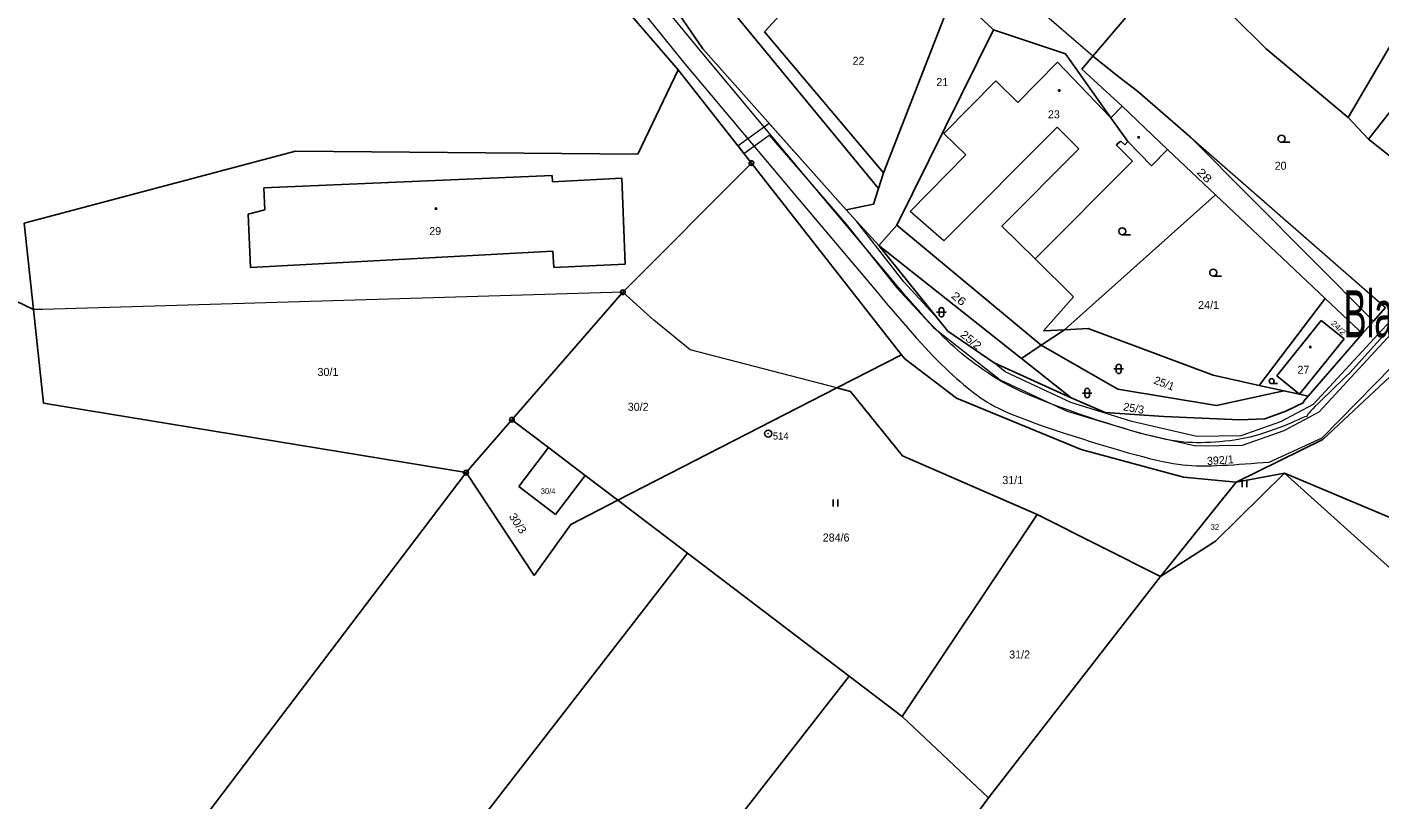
# Model space of a CAD drawing. Extents: x -504006 to -501322, y -1128098 to -1124665.
# Drawn here: x -503112.2 to -502824.9, y -1126824.4 to -1126660.2 of the extents above; entities that cross this region are included whole.
import ezdxf
from ezdxf.enums import TextEntityAlignment as Align

# ---------------------------------------------------------------- set-up
doc = ezdxf.new("R2010")
doc.units = 0
doc.header["$LTSCALE"] = 0.68
for name, color, linetype, lineweight in [('1', 7, 'Continuous', 25), ('13', 7, 'Continuous', 13), ('3', 7, 'Continuous', 25), ('4', 7, 'Continuous', 13), ('5', 7, 'Continuous', 25), ('7', 7, 'Continuous', 13), ('8', 7, 'Continuous', 25)]:
    doc.layers.add(name, color=color, linetype=linetype, lineweight=lineweight)
doc.layers.add('2', color=7, linetype='Continuous')

msp = doc.modelspace()

# ---------------------------------------------------------------- linework, layer by layer
at = {"layer": '1'}
for p, q in [((-503013.32, -1126594.85), (-502931.36, -1126694.5)), ((-502999.07, -1126640.12), (-502973.88, -1126669.24)), ((-502937.19, -1126641.28), (-502955.59, -1126661.2)), ((-502968.7, -1126664.8), (-502982.84, -1126644.09)), ((-502870.5, -1126648.32), (-502885.81, -1126666.36)), ((-502906.97, -1126660.74), (-502914.51, -1126653.68)), ((-502831.61, -1126679.37), (-502817.44, -1126655.15)), ((-502930.28, -1126691.17), (-502916.98, -1126657.04)), ((-502848.99, -1126664.8), (-502856.19, -1126657.72)), ((-502930.28, -1126691.17), (-502955.59, -1126661.2)), ((-502906.97, -1126660.74), (-502927.48, -1126702.25)), ((-502891.65, -1126665.9), (-502906.97, -1126660.74)), ((-502938.24, -1126699.01), (-502968.7, -1126664.8)), ((-502831.61, -1126679.37), (-502848.99, -1126664.8)), ((-502881.99, -1126679.47), (-502891.65, -1126665.9)), ((-502885.81, -1126666.36), (-502888.14, -1126669.11)), ((-502880.27, -1126670.83), (-502885.81, -1126666.36)), ((-502812.52, -1126665.24), (-502827.32, -1126684)), ((-502982.48, -1126687.18), (-502973.88, -1126669.24)), ((-502958.35, -1126689.07), (-502973.88, -1126669.24)), ((-502888.14, -1126669.11), (-502879.6, -1126676.99)), ((-502876.33, -1126673.81), (-502880.27, -1126670.83)), ((-502865.13, -1126683.59), (-502876.33, -1126673.81)), ((-502879.6, -1126676.99), (-502870.01, -1126686.18)), ((-502827.32, -1126684), (-502831.61, -1126679.37)), ((-502878.37, -1126684.47), (-502881.99, -1126679.47)), ((-502879.86, -1126684.43), (-502880.87, -1126685.19)), ((-502880.87, -1126685.19), (-502877.41, -1126688.64)), ((-502879.07, -1126685.19), (-502879.86, -1126684.43)), ((-502878.37, -1126684.47), (-502879.07, -1126685.19)), ((-502873.4, -1126689.68), (-502878.37, -1126684.47)), ((-502826.25, -1126722.68), (-502865.13, -1126683.59)), ((-502813.5, -1126695.01), (-502827.32, -1126684)), ((-503112.79, -1126701.87), (-503055.2, -1126686.52)), ((-503055.2, -1126686.52), (-502982.48, -1126687.18)), ((-502870.01, -1126686.18), (-502873.4, -1126689.68)), ((-502870.01, -1126686.18), (-502859.76, -1126695.85)), ((-502958.35, -1126689.07), (-502985.65, -1126716.51)), ((-502926.46, -1126729.81), (-502958.35, -1126689.07)), ((-502877.41, -1126688.64), (-502898.11, -1126709.4)), ((-503061.88, -1126694.31), (-503000.67, -1126691.74)), ((-503000.67, -1126691.74), (-503000.61, -1126693.03)), ((-503000.61, -1126693.03), (-502985.87, -1126692.31)), ((-502985.87, -1126692.31), (-502985.14, -1126710.59)), ((-502931.36, -1126694.5), (-502930.28, -1126691.17)), ((-503061.69, -1126699), (-503061.88, -1126694.31)), ((-502932.43, -1126697.8), (-502931.36, -1126694.5)), ((-502859.76, -1126695.85), (-502836.46, -1126717.85)), ((-503065.21, -1126699.95), (-503061.69, -1126699)), ((-502938.24, -1126699.01), (-502932.43, -1126697.8)), ((-502931.32, -1126706.59), (-502938.24, -1126699.01)), ((-503110.83, -1126720.22), (-503112.79, -1126701.87)), ((-503064.71, -1126711.28), (-503065.21, -1126699.95)), ((-502927.48, -1126702.25), (-502931.32, -1126706.59)), ((-502896.83, -1126727.8), (-502927.48, -1126702.25)), ((-503000.5, -1126707.79), (-503064.71, -1126711.28)), ((-503000.35, -1126711.25), (-503000.5, -1126707.79)), ((-502916.65, -1126724.77), (-502931.32, -1126706.59)), ((-502931.32, -1126706.59), (-502901, -1126730.57)), ((-503130.35, -1126710.8), (-503110.83, -1126720.22)), ((-502985.14, -1126710.59), (-503000.35, -1126711.25)), ((-502898.11, -1126709.4), (-502889.92, -1126717.49)), ((-502889.92, -1126717.49), (-502896.32, -1126724.74)), ((-502836.46, -1126717.85), (-502850.54, -1126736.32)), ((-502836.46, -1126717.85), (-502830.3, -1126723.67)), ((-503108.71, -1126740.11), (-503110.83, -1126720.22)), ((-502837.31, -1126722.5), (-502846.79, -1126734.26)), ((-502832.45, -1126726.42), (-502837.31, -1126722.5)), ((-502826.25, -1126722.68), (-502823.71, -1126719.75)), ((-502906.76, -1126731.49), (-502916.65, -1126724.77)), ((-502891.83, -1126724.49), (-502896.83, -1126727.8)), ((-502896.32, -1126724.74), (-502891.83, -1126724.49)), ((-502886.84, -1126724.2), (-502891.83, -1126724.49)), ((-502860.28, -1126734.18), (-502886.84, -1126724.2)), ((-502840.09, -1126738.62), (-502828.54, -1126725.32)), ((-502836.98, -1126747.85), (-502810.72, -1126723.17)), ((-502830.3, -1126723.67), (-502828.54, -1126725.32)), ((-502828.54, -1126725.32), (-502826.25, -1126722.68)), ((-502901, -1126730.57), (-502896.83, -1126727.8)), ((-502880.51, -1126737.14), (-502896.83, -1126727.8)), ((-502841.94, -1126738.21), (-502832.45, -1126726.42)), ((-502926.46, -1126729.81), (-502940.21, -1126736.86)), ((-502925.78, -1126730.68), (-502926.46, -1126729.81)), ((-502914.77, -1126739.04), (-502925.78, -1126730.68)), ((-502890.45, -1126738.93), (-502901, -1126730.57)), ((-502890.45, -1126738.93), (-502906.76, -1126731.49)), ((-502940.21, -1126736.86), (-502986.73, -1126760.73)), ((-502937.32, -1126737.61), (-502940.21, -1126736.86)), ((-502850.54, -1126736.32), (-502860.28, -1126734.18)), ((-502845.26, -1126737.48), (-502850.54, -1126736.32)), ((-502846.79, -1126734.26), (-502841.94, -1126738.21)), ((-502926.23, -1126751.26), (-502937.32, -1126737.61)), ((-502888.33, -1126749.91), (-502914.77, -1126739.04)), ((-502883.24, -1126742.1), (-502890.45, -1126738.93)), ((-502859.6, -1126740.57), (-502880.51, -1126737.14)), ((-502845.26, -1126737.48), (-502859.6, -1126740.57)), ((-502841.94, -1126738.21), (-502845.26, -1126737.48)), ((-502840.09, -1126738.62), (-502841.94, -1126738.21)), ((-502841.07, -1126739.74), (-502840.09, -1126738.62)), ((-502841.04, -1126739.96), (-502841.07, -1126739.74)), ((-503018.97, -1126754.86), (-503108.71, -1126740.11)), ((-502870.75, -1126742.95), (-502883.24, -1126742.1)), ((-502844.83, -1126741.83), (-502849.32, -1126743.4)), ((-502841.04, -1126739.96), (-502844.83, -1126741.83)), ((-503001.44, -1126749.54), (-503009.21, -1126743.62)), ((-502854.64, -1126743.63), (-502870.75, -1126742.95)), ((-502849.32, -1126743.4), (-502854.64, -1126743.63)), ((-502855.4, -1126756.88), (-502836.98, -1126747.85)), ((-503007.75, -1126757.83), (-503001.44, -1126749.54)), ((-502993.68, -1126755.45), (-503001.44, -1126749.54)), ((-502897.66, -1126763.76), (-502926.23, -1126751.26)), ((-502866.61, -1126755.83), (-502888.33, -1126749.91)), ((-503018.97, -1126754.86), (-503103.89, -1126866.73)), ((-503004.52, -1126776.71), (-503018.97, -1126754.86)), ((-502993.68, -1126755.45), (-502999.99, -1126763.74)), ((-502986.73, -1126760.73), (-502993.68, -1126755.45)), ((-502855.4, -1126756.88), (-502871.45, -1126776.94)), ((-502855.4, -1126756.88), (-502866.61, -1126755.83)), ((-502845.16, -1126755), (-502859.81, -1126769.39)), ((-502845.16, -1126755), (-502855.4, -1126756.88)), ((-502813.43, -1126768.36), (-502845.16, -1126755)), ((-502800.39, -1126795.2), (-502845.16, -1126755)), ((-502999.99, -1126763.74), (-503007.75, -1126757.83)), ((-502986.73, -1126760.73), (-502996.74, -1126765.87)), ((-502971.93, -1126772), (-502986.73, -1126760.73)), ((-502897.66, -1126763.76), (-502926.36, -1126806.68)), ((-502871.45, -1126776.94), (-502897.66, -1126763.76)), ((-502996.74, -1126765.87), (-503004.52, -1126776.71)), ((-502859.81, -1126769.39), (-502871.45, -1126776.94)), ((-502971.93, -1126772), (-503069.17, -1126897.27)), ((-502937.59, -1126798.13), (-502971.93, -1126772)), ((-502908.02, -1126823.96), (-502871.45, -1126776.94)), ((-502937.59, -1126798.13), (-503097.68, -1127003.42)), ((-502926.36, -1126806.68), (-502937.59, -1126798.13)), ((-502926.36, -1126806.68), (-502908.02, -1126823.96)), ((-503047.81, -1127013.5), (-502908.02, -1126823.96))]:
    msp.add_line(p, q, dxfattribs=at)
msp.add_lwpolyline([(-502985.65, -1126716.51), (-503009.21, -1126743.62), (-503018.97, -1126754.86)], dxfattribs=at)
at = {"layer": '13'}
msp.add_lwpolyline([(-502813.13, -1126712.33), (-502839.03, -1126740.37), (-502845.99, -1126744.05), (-502854.43, -1126747.05), (-502863.74, -1126747.16), (-502877.54, -1126744), (-502890.54, -1126739.92), (-502904.44, -1126733.41), (-502906.76, -1126731.49), (-502916.65, -1126724.77), (-502918.65, -1126722.29), (-502925.95, -1126714.32), (-502936.05, -1126701.41), (-502937.4, -1126699.93), (-502938.24, -1126699.01), (-502954.56, -1126680.68), (-502961.19, -1126685.44), (-502959.96, -1126687.02), (-502954.6, -1126683.17), (-502938.21, -1126702.07), (-502927.47, -1126715.62), (-502919.65, -1126724.05), (-502905.5, -1126735.13), (-502891.26, -1126741.78), (-502876, -1126746.4), (-502863.96, -1126749.16), (-502854.07, -1126749.05), (-502845.19, -1126745.89), (-502837.79, -1126741.97), (-502812.25, -1126714.32)], dxfattribs=at)
at = {"layer": '3'}
for p, q in [((-502845.753, -1126684.67), (-502844.003, -1126684.67)), ((-502879.583, -1126704.33), (-502877.833, -1126704.33)), ((-502860.273, -1126713.11), (-502858.523, -1126713.11)), ((-502919.011, -1126720.781), (-502917.009, -1126720.781)), ((-502918.511, -1126720.281), (-502918.511, -1126721.282)), ((-502917.509, -1126721.282), (-502917.509, -1126720.281)), ((-502881.351, -1126732.811), (-502879.349, -1126732.811)), ((-502880.851, -1126732.311), (-502880.851, -1126733.312)), ((-502879.849, -1126733.312), (-502879.849, -1126732.311)), ((-502847.855, -1126735.93), (-502846.63, -1126735.93)), ((-502888.041, -1126737.941), (-502886.039, -1126737.941)), ((-502887.541, -1126737.441), (-502887.541, -1126738.442)), ((-502886.539, -1126738.442), (-502886.539, -1126737.441)), ((-502854.121, -1126757.95), (-502854.121, -1126756.45)), ((-502853.12, -1126757.95), (-502853.12, -1126756.45)), ((-502941.021, -1126762.03), (-502941.021, -1126760.53)), ((-502940.02, -1126762.03), (-502940.02, -1126760.53))]:
    msp.add_line(p, q, dxfattribs=at)
for centre, radius in [((-502845.7529, -1126683.9198), 0.75), ((-502879.5829, -1126703.5798), 0.75), ((-502860.2729, -1126712.3598), 0.75), ((-502847.855, -1126735.4049), 0.525)]:
    msp.add_circle(centre, radius, dxfattribs=at)
for centre, start, end in [((-502918.01, -1126720.2809), 0, 180), ((-502918.01, -1126721.2809), 180, 359.98789), ((-502880.35, -1126732.3109), 0, 180), ((-502880.35, -1126733.3109), 180, 359.98789), ((-502887.04, -1126737.4409), 0, 180), ((-502887.04, -1126738.4409), 180, 359.98789)]:
    msp.add_arc(centre, 0.5, start, end, dxfattribs=at)
at = {"layer": '4'}
for p, q in [((-502998.05, -1126636.32), (-502972.5, -1126668)), ((-502969.2, -1126665.2), (-502995.2, -1126633.59)), ((-502885.81, -1126666.36), (-502907.62, -1126647.54)), ((-502944.8, -1126694.4), (-502969.2, -1126665.2)), ((-502901.79, -1126676.19), (-502893.34, -1126667.61)), ((-502893.34, -1126667.61), (-502881.99, -1126679.47)), ((-502972.5, -1126668), (-502948.3, -1126696.8)), ((-502917.48, -1126682.77), (-502906.42, -1126671.62)), ((-502906.42, -1126671.62), (-502901.79, -1126676.19)), ((-502881.99, -1126679.47), (-502879.6, -1126676.99)), ((-502893.4, -1126681.47), (-502917.47, -1126705.63)), ((-502888.79, -1126686.06), (-502893.4, -1126681.47)), ((-502912.8, -1126687.36), (-502917.48, -1126682.77)), ((-502865.13, -1126683.59), (-502823.71, -1126719.75)), ((-502924.67, -1126699.4), (-502912.8, -1126687.36)), ((-502905.17, -1126702.51), (-502888.79, -1126686.06)), ((-502928.41, -1126713.99), (-502944.8, -1126694.4)), ((-502891.83, -1126724.49), (-502859.76, -1126695.85)), ((-502948.3, -1126696.8), (-502931.6, -1126716.6)), ((-502917.47, -1126705.63), (-502924.67, -1126699.4)), ((-502898.11, -1126709.4), (-502905.17, -1126702.51)), ((-502812.6, -1126712.9), (-502831.2, -1126733.6)), ((-502985.65, -1126716.51), (-503108.83, -1126720.16)), ((-502979.08, -1126722.44), (-502985.65, -1126716.51)), ((-502837.16, -1126747.49), (-502806.8, -1126716.5)), ((-503108.83, -1126720.16), (-503110.83, -1126720.22)), ((-502971.37, -1126728.77), (-502979.08, -1126722.44)), ((-502940.21, -1126736.86), (-502971.37, -1126728.77)), ((-502848.38, -1126752.6), (-502837.16, -1126747.49))]:
    msp.add_line(p, q, dxfattribs=at)
for points in [[(-502931.6, -1126716.6), (-502930.664, -1126717.711), (-502929.718, -1126718.833), (-502928.785, -1126719.936), (-502927.855, -1126721.031), (-502926.918, -1126722.128), (-502925.996, -1126723.198), (-502925.081, -1126724.252), (-502924.161, -1126725.299), (-502923.259, -1126726.311), (-502922.367, -1126727.299), (-502921.473, -1126728.27), (-502920.6, -1126729.2), (-502919.739, -1126730.097), (-502918.879, -1126730.972), (-502918.042, -1126731.804), (-502917.217, -1126732.604), (-502916.396, -1126733.381), (-502915.598, -1126734.118), (-502914.814, -1126734.823), (-502914.036, -1126735.504), (-502913.281, -1126736.147), (-502912.541, -1126736.759), (-502911.808, -1126737.348), (-502911.1, -1126737.9), (-502910.406, -1126738.423), (-502909.705, -1126738.927), (-502908.999, -1126739.407), (-502908.266, -1126739.873), (-502907.48, -1126740.337), (-502906.647, -1126740.793), (-502905.743, -1126741.253), (-502904.74, -1126741.726), (-502903.647, -1126742.208), (-502902.439, -1126742.71), (-502901.084, -1126743.243), (-502899.6, -1126743.8), (-502897.963, -1126744.391), (-502896.17, -1126745.018), (-502894.289, -1126745.658), (-502892.325, -1126746.311), (-502890.279, -1126746.978), (-502888.224, -1126747.633), (-502886.163, -1126748.279), (-502884.096, -1126748.915), (-502882.098, -1126749.517), (-502880.169, -1126750.086), (-502878.313, -1126750.621), (-502876.6, -1126751.1), (-502875.026, -1126751.525), (-502873.565, -1126751.901), (-502872.237, -1126752.223), (-502871.007, -1126752.498), (-502869.847, -1126752.732), (-502868.767, -1126752.923), (-502867.74, -1126753.076), (-502866.736, -1126753.198), (-502865.764, -1126753.286), (-502864.797, -1126753.347), (-502863.806, -1126753.385), (-502862.8, -1126753.4), (-502861.754, -1126753.397), (-502860.656, -1126753.377), (-502859.535, -1126753.343), (-502858.382, -1126753.295), (-502857.185, -1126753.234), (-502855.978, -1126753.163), (-502854.75, -1126753.084), (-502853.488, -1126752.995), (-502852.228, -1126752.902), (-502850.956, -1126752.804), (-502849.662, -1126752.702), (-502848.38, -1126752.6)], [(-502921.017, -1126722.428), (-502921.918, -1126721.436), (-502922.82, -1126720.427), (-502923.732, -1126719.395), (-502924.664, -1126718.331), (-502925.592, -1126717.263), (-502926.525, -1126716.183), (-502927.472, -1126715.082), (-502928.41, -1126713.99)], [(-502831.2, -1126733.6), (-502832.142, -1126734.499), (-502833.086, -1126735.401), (-502834, -1126736.276), (-502834.887, -1126737.127), (-502835.747, -1126737.957), (-502836.551, -1126738.737), (-502837.3, -1126739.469), (-502837.993, -1126740.154), (-502838.604, -1126740.766), (-502839.133, -1126741.308), (-502839.575, -1126741.776), (-502839.91, -1126742.15), (-502840.14, -1126742.433), (-502840.281, -1126742.636), (-502840.347, -1126742.767), (-502840.359, -1126742.843), (-502840.337, -1126742.875), (-502840.299, -1126742.878), (-502840.264, -1126742.864), (-502840.251, -1126742.845), (-502840.28, -1126742.837), (-502840.367, -1126742.851), (-502840.536, -1126742.901), (-502840.8, -1126743), (-502841.175, -1126743.157), (-502841.664, -1126743.37), (-502842.245, -1126743.627), (-502842.915, -1126743.923), (-502843.673, -1126744.253), (-502844.493, -1126744.602), (-502845.374, -1126744.967), (-502846.319, -1126745.343), (-502847.295, -1126745.714), (-502848.304, -1126746.076), (-502849.351, -1126746.427), (-502850.4, -1126746.75), (-502851.456, -1126747.043), (-502852.529, -1126747.308), (-502853.59, -1126747.54), (-502854.649, -1126747.745), (-502855.717, -1126747.924), (-502856.766, -1126748.075), (-502857.805, -1126748.202), (-502858.846, -1126748.305), (-502859.859, -1126748.385), (-502860.856, -1126748.443), (-502861.845, -1126748.482), (-502862.8, -1126748.5), (-502863.733, -1126748.5), (-502864.666, -1126748.478), (-502865.588, -1126748.432), (-502866.523, -1126748.358), (-502867.494, -1126748.253), (-502868.492, -1126748.115), (-502869.54, -1126747.941), (-502870.665, -1126747.724), (-502871.851, -1126747.466), (-502873.124, -1126747.163), (-502874.514, -1126746.805), (-502876, -1126746.4), (-502877.605, -1126745.941), (-502879.334, -1126745.427), (-502881.124, -1126744.878), (-502882.973, -1126744.295), (-502884.884, -1126743.676), (-502886.788, -1126743.045), (-502888.687, -1126742.4), (-502890.582, -1126741.74), (-502892.406, -1126741.089), (-502894.16, -1126740.445), (-502895.842, -1126739.808), (-502897.39, -1126739.2), (-502898.809, -1126738.619), (-502900.12, -1126738.056), (-502901.302, -1126737.522), (-502902.384, -1126737.008), (-502903.388, -1126736.504), (-502904.302, -1126736.019), (-502905.149, -1126735.545), (-502905.95, -1126735.072), (-502906.698, -1126734.609), (-502907.413, -1126734.147), (-502908.116, -1126733.678), (-502908.8, -1126733.21), (-502909.484, -1126732.734), (-502910.18, -1126732.241), (-502910.872, -1126731.739), (-502911.57, -1126731.22), (-502912.285, -1126730.673), (-502913.001, -1126730.108), (-502913.727, -1126729.515), (-502914.476, -1126728.883), (-502915.229, -1126728.225), (-502915.998, -1126727.529), (-502916.795, -1126726.782), (-502917.6, -1126726), (-502918.425, -1126725.171), (-502919.28, -1126724.288), (-502920.141, -1126723.376), (-502921.017, -1126722.428)]]:
    msp.add_lwpolyline(points, dxfattribs=at)
at = {"layer": '5'}
for centre in [(-502892.9768, -1126673.6592), (-502876.0868, -1126683.6092), (-503025.3268, -1126698.7492), (-502839.6368, -1126728.1492)]:
    msp.add_circle(centre, 0.175, dxfattribs=at)
at = {"layer": '8'}
for centre, radius in [((-502958.35, -1126689.0699), 0.5), ((-502958.35, -1126689.0699), 0.0303), ((-502985.65, -1126716.5099), 0.5), ((-502985.65, -1126716.5099), 0.0303), ((-503009.21, -1126743.6199), 0.5), ((-503009.21, -1126743.6199), 0.0303), ((-502954.79, -1126746.5598), 0.75), ((-502954.79, -1126746.5598), 0.03), ((-503018.97, -1126754.8599), 0.5), ((-503018.97, -1126754.8599), 0.0303)]:
    msp.add_circle(centre, radius, dxfattribs=at)

# ---------------------------------------------------------------- texts
at = {"layer": '2'}
for s, height, p in [('22', 1.7, (-502935.599, -1126668.195)), ('21', 1.7, (-502917.819, -1126672.715)), ('23', 1.7, (-502894.119, -1126679.575)), ('20', 1.7, (-502845.959, -1126690.495)), ('29', 1.7, (-503025.519, -1126704.375)), ('24/1', 1.7, (-502861.249, -1126720.085)), ('30/1', 1.7, (-503048.289, -1126734.305)), ('27', 1.7, (-502841.119, -1126733.855)), ('30/2', 1.7, (-502982.409, -1126741.715)), ('31/1', 1.7, (-502902.849, -1126757.285)), ('30/4', 1.2, (-503001.54, -1126759.39)), ('284/6', 1.7, (-502940.36, -1126769.495)), ('32', 1.2, (-502859.919, -1126767.01)), ('31/2', 1.7, (-502901.389, -1126794.345))]:
    msp.add_text(s, height=height, dxfattribs=at).set_placement(p, align=Align.CENTER)
for s, height, rotation, width, p in [('28', 1.7, 316, 1.3, (-502862.7245, -1126692.3261)), ('26', 1.7, 321, 1.25, (-502914.8449, -1126718.5499)), ('25/2', 1.7, 321, 1.1, (-502912.2344, -1126727.3307)), ('24/2', 1.2, 316, 1.15, (-502834.0658, -1126724.5005)), ('30/3', 1.7, 303, 1.05, (-503008.6726, -1126766.0966))]:
    msp.add_text(s, height=height, rotation=rotation, dxfattribs=dict(at, width=width)).set_placement(p, align=Align.CENTER)
for s, rotation, p in [('25/1', 339, (-502870.9866, -1126736.676)), ('25/3', 350, (-502877.2986, -1126742.0013))]:
    msp.add_text(s, height=1.7, rotation=rotation, dxfattribs=at).set_placement(p, align=Align.CENTER)
msp.add_text('392/1', height=1.7, rotation=4, dxfattribs=at).set_placement((-502861.54, -1126753.243))
at = {"layer": '7', "width": 0.55}
msp.add_text('Blahutovice 604968', height=10, dxfattribs=at).set_placement((-502800.3, -1126726.093), align=Align.CENTER)
at = {"layer": '8'}
msp.add_text('514', height=1.5, dxfattribs=at).set_placement((-502950.459, -1126747.825), align=Align.RIGHT)

doc.saveas('drawing.dxf')
